(* Logix 5000 project; controller ILX69_PBM vendor 1 type 14 code 77 rev 16.3; software revision 16.05 *)
// ILX69-PBM Profibus Master Sample Ladder

TASK MainTask (continuous, watchdog 500 ms) : MainProgram

MODULES
   Controller : vendor 1 type 14 code 77 (CompactLogixL32EController 0, rev 16.3)
      LocalENB : 1769-L32E Ethernet Port (CompactLogixL32Ethernet 1, rev 16.3)
      Local : CompactBus (CompactVirtualAdapter 3, rev 16.3, Input RPI 5 ms)
         PBM : 1769-MODULE (Compact 1, rev 1.1, Output RPI 2 ms)   // Profibus Master
END_MODULES

TYPE EDIT_ILX69PBM_DATA :   // Array size should be the same as the address table size in fdt Configuration Manager.
STRUCT
   INPUT : SINT[5712];   // Input Data
   OUTPUT : SINT[5760];   // Output Data
END_STRUCT
END_TYPE

TYPE ILX69PBM_CONTROL :
STRUCT
   DisableProfibus : BOOL;   // Halt Profibus Communication
   ColdBoot : BOOL;   // Cold Boot Reset
   BackplaneBlock : ILX69PBM_CONTROL_BACKPLANE;   // Block Control
   DPV1 : ILX69PBM_CONTROL_DPV1;   // DPV1 Data
   SlaveDiagnostic : ILX69PBM_CONTROL_SLAVEDIAG;   // Slave Diagnostic Data
   SlaveControl : ILX69PBM_CONTROL_SLAVECONTROL;   // Slave Control
END_STRUCT
END_TYPE

TYPE ILX69PBM_CONTROL_BACKPLANE :   // Backplane Block Control
STRUCT
   DisableAutoTransfer : BOOL;   // Disable Automatic Block Transfer
   Input : ILX69PBM_CONTROL_BACKPLANE_INPUT;
   Output : ILX69PBM_CONTROL_BACKPLANE_OUTPUT;
END_STRUCT
END_TYPE

TYPE ILX69PBM_CONTROL_BACKPLANE_INPUT :
STRUCT
   BlockID : SINT;   // Requested Input Block Number. Use when DisableAutoTransfer is set.
   ReadBlock : BOOL;   // Initiate to receive the data from the requested Input Block Number. Use when DisableAutoTransfer is set.
END_STRUCT
END_TYPE

TYPE ILX69PBM_CONTROL_BACKPLANE_OUTPUT :
STRUCT
   BlockID : SINT;   // Command Output Block Number. Use when DisableAutoTransfer is set.
   WriteBlock : BOOL;   // Send current commanded output block to module. Use when DisableAutoTransfer is set.
   CommitToProfibus : BOOL;   // Commit output block data to Profibus. Use when DisableAutoTransfer is set.
END_STRUCT
END_TYPE

TYPE ILX69PBM_CONTROL_DPV1 :   // DPV1
STRUCT
   Read : ILX69PBM_CONTROL_DPV1_READ;   // DPV1 Read Request
   Write : ILX69PBM_CONTROL_DPV1_WRITE;   // DPV1 Write Request
   Alarm : ILX69PBM_CONTROL_DPV1_ALARM;   // DPV1 Alarm Response Request
END_STRUCT
END_TYPE

TYPE ILX69PBM_CONTROL_DPV1_ALARM :   // Alarm Response
STRUCT
   Initiate : BOOL;   // Initiate DPV1 Alarm Response
   MSGStatus : ILX69PBM_MESSAGE_STATUS;   // Message Status
   Request : ILX69PBM_CONTROL_DPV1_ALARM_REQUEST;   // Request
   Response : ILX69PBM_CONTROL_DPV1_ALARM_RESPONSE;   // Response
END_STRUCT
END_TYPE

TYPE ILX69PBM_CONTROL_DPV1_ALARM_REQUEST :   // DPV1 Alarm Response Request
STRUCT
   Status : DINT;   // Status
   Command : DINT;   // Message Command. Set to 0x221C
   SlaveAddress : SINT;   // Slave Address
   AlarmType : SINT;   // Type of the received alarm
   SlotNumber : SINT;   // Slot number of module causing the alarm
   Specifier : SINT;   // Alarm specifier
   Function : SINT;   // Reserved
   Reserved : SINT[3];   // Reserved
END_STRUCT
END_TYPE

TYPE ILX69PBM_CONTROL_DPV1_ALARM_RESPONSE :   // DPV1 Alarm Response Confirm
STRUCT
   Status : DINT;   // Status 0=OK
   Command : DINT;   // Should be 0x221D
   SlaveAddress : SINT;   // Slave Address
   AlarmType : SINT;   // Type of alarm received
   SlotNumber : SINT;   // Slot Number of module causing the alarm
   Specifier : SINT;   // Alarm specifier
   Function : SINT;   // Reserved
   ErrorDecode : SINT;   // 128 indicates DPV1 error
   ErrorCode1 : SINT;   // Error Code 1
   ErrorCode2 : SINT;   // Error Code 2
END_STRUCT
END_TYPE

TYPE ILX69PBM_CONTROL_DPV1_READ :   // DPV1 Read
STRUCT
   Initiate : BOOL;   // Initiate DPV1 Slave Read
   MSGStatus : ILX69PBM_MESSAGE_STATUS;   // Message Status
   Request : ILX69PBM_CONTROL_DPV1_READ_REQUEST;   // Request
   Response : ILX69PBM_CONTROL_DPV1_READ_RESPONSE;   // Response
END_STRUCT
END_TYPE

TYPE ILX69PBM_CONTROL_DPV1_READ_REQUEST :   // DPV1 Read Request
STRUCT
   Status : DINT;   // Status
   Command : DINT;   // Message Command. Set to 0x2210
   SlaveAddress : SINT;   // Slave Address
   SlotNumber : SINT;   // Slot Number
   Index : SINT;   // Index
   Length : SINT;   // Length
END_STRUCT
END_TYPE

TYPE ILX69PBM_CONTROL_DPV1_READ_RESPONSE :   // DPV1 Read Response
STRUCT
   Status : DINT;   // Status
   Command : DINT;   // Should be 0x2211
   SlaveAddress : SINT;   // Slave Address
   SlotNumber : SINT;   // Slot Number
   Index : SINT;   // Index
   Length : SINT;   // Length
   Data : SINT[100];   // Data or Error Codes (first 2 bytes)
END_STRUCT
END_TYPE

TYPE ILX69PBM_CONTROL_DPV1_WRITE :   // DPV1 Write
STRUCT
   Initiate : BOOL;   // Initiate DPV1 Slave Write
   MSGStatus : ILX69PBM_MESSAGE_STATUS;   // Message Status
   Request : ILX69PBM_CONTROL_DPV1_WRITE_REQUEST;   // Request
   Response : ILX69PBM_CONTROL_DPV1_WRITE_RESPONSE;   // Response
END_STRUCT
END_TYPE

TYPE ILX69PBM_CONTROL_DPV1_WRITE_REQUEST :   // DPV1 Write Request
STRUCT
   Status : DINT;   // Status
   Command : DINT;   // Message Command. Set to 0x2212
   SlaveAddress : SINT;   // Slave Address
   SlotNumber : SINT;   // Slot Number
   Index : SINT;   // Index
   Length : SINT;   // Length
   Data : SINT[100];   // Write Data
END_STRUCT
END_TYPE

TYPE ILX69PBM_CONTROL_DPV1_WRITE_RESPONSE :   // DPV1 Write Response
STRUCT
   Status : DINT;   // Status 0=OK
   Command : DINT;   // Should return 0x2213
   SlaveAddress : SINT;   // Slave Address
   SlotNumber : SINT;   // Slot Number
   Index : SINT;   // Index
   Length : SINT;   // Length
   ErrorDecode : SINT;   // Error 128=DPV1 error
   ErrorCode1 : SINT;   // Error Code 1
   ErrorCode2 : SINT;   // Error Code 2
   Reserved : SINT;   // Reserved
END_STRUCT
END_TYPE

TYPE ILX69PBM_CONTROL_SLAVECONTROL :   // Cyclic Slave Control
STRUCT
   SetSlaveControl : ILX69PBM_CONTROL_SLAVECONTROLBLOCK;   // Slave Control via Block Transfer
   SetSlaveControl_MSG : ILX69PBM_CONTROL_SLAVECONTROLMSG;   // Slave Global Control via MSG
END_STRUCT
END_TYPE

TYPE ILX69PBM_CONTROL_SLAVECONTROLBLOCK :
STRUCT
   Initiate : BOOL;   // Initiate Slave Control
   Address : SINT;   // Slave Address
   MSGStatus : ILX69PBM_MESSAGE_STATUS;   // Message Status
   SlaveCommand : ILX69PBM_CONTROL_SLAVECONTROLBLOCK_CMD;   // Slave Control Command
END_STRUCT
END_TYPE

TYPE ILX69PBM_CONTROL_SLAVECONTROLBLOCK_CMD :   // Slave Control Block Command
STRUCT
   ClearData : BOOL;   // Clear Output Data
   UnFreeze : BOOL;   // Unfreeze Input Data
   Freeze : BOOL;   // Freeze Input Data
   UnSync : BOOL;   // Neutralize the sync command or Unsync
   Sync : BOOL;   // Freeze Output Data until sync command is neutralized
   GroupSelect : SINT;   // Group Select
END_STRUCT
END_TYPE

TYPE ILX69PBM_CONTROL_SLAVECONTROLMSG :   // DPV0 Global Control
STRUCT
   Initiate : BOOL;   // Initiate Global Control
   MSGStatus : ILX69PBM_MESSAGE_STATUS;   // Message Status
   Request : ILX69PBM_CONTROL_SLAVECONTROLMSG_REQUEST;   // Request
   Response : ILX69PBM_CONTROL_SLAVECONTROLMSG_RESPONS;   // Response
END_STRUCT
END_TYPE

TYPE ILX69PBM_CONTROL_SLAVECONTROLMSG_CMD :   // Slave Control Message Command
STRUCT
   UnFreeze : BOOL;   // Unfreeze Input Data
   Freeze : BOOL;   // Freeze Input Data
   UnSync : BOOL;   // Neutralize the sync command or Unsync
   Sync : BOOL;   // Freeze Output Data until sync command is neutralized
   GroupSelect : SINT;   // Group Select
END_STRUCT
END_TYPE

TYPE ILX69PBM_CONTROL_SLAVECONTROLMSG_REQUEST :   // Global Control Request
STRUCT
   Status : DINT;   // Status
   Command : DINT;   // Message Command. Set to 0x2220
   Address : DINT;   // Slave Address
   Reserved : ILX69PBM_CONTROL_SLAVECONTROLMSG_RSVD;   // Reserved
   SlaveCommand : ILX69PBM_CONTROL_SLAVECONTROLMSG_CMD;   // Slave Command
END_STRUCT
END_TYPE

TYPE ILX69PBM_CONTROL_SLAVECONTROLMSG_RESPONS :   // DPV0 Slave Global Control Confirm
STRUCT
   Status : DINT;   // Status 0=OK
   Command : DINT;   // Should return 0x2221
END_STRUCT
END_TYPE

TYPE ILX69PBM_CONTROL_SLAVECONTROLMSG_RSVD :
STRUCT
   SyncCommand : DINT;   // Sync Command
   FreezeCommand : DINT;   // Freeze Command
   GroupSelect : DINT;   // Group selection
END_STRUCT
END_TYPE

TYPE ILX69PBM_CONTROL_SLAVEDIAG :   // Diagnostic Data
STRUCT
   GetSlaveDiag : ILX69PBM_CONTROL_SLAVEDIAG_BLOCK;   // Slave Diagnostic Data via Block Transfer
   GetSlaveDiagExtended_MSG : ILX69PBM_CONTROL_SLAVEDIAG_EXT;   // Slave Extended Diagnostic via MSG
END_STRUCT
END_TYPE

TYPE ILX69PBM_CONTROL_SLAVEDIAG_BLOCK :   // Slave Diagnostic Data
STRUCT
   Initiate : BOOL;   // Initiate Slave Diagnostic
   Address : SINT;   // Slave Address
   Function : SINT;   // Function: 0-Requested from Master 1-Requested from Slave
   MSGStatus : ILX69PBM_MESSAGE_STATUS;   // Message Status
   Response : ILX69PBM_CONTROL_SLAVEDIAG_BLOCKRESPONSE;   // Diagnostic Response
END_STRUCT
END_TYPE

TYPE ILX69PBM_CONTROL_SLAVEDIAG_BLOCKRESPONSE :   // Slave Diagnostic Reponse
STRUCT
   SlaveAddress : SINT;   // Slave address
   SlaveDiagnosticFailure : SINT;   // Slave Diag Failure
   StationNotExist : BOOL;   // No response
   StationNotReady : BOOL;   // Station not ready
   ConfigurationFault : BOOL;   // Configuration faulty
   ExtendedDiagnostic : BOOL;   // Extended diagnostic
   SyncFreezeNoSupport : BOOL;   // Sync,Freeze not supported
   InvalidResponse : BOOL;   // Response faulty
   ParamterFault : BOOL;   // Parameters faulty
   MasterLock : BOOL;   // Locked by a master
   ParameterRequest : BOOL;   // Request new parameter
   StaticDiagnostic : BOOL;   // Static diagnostic
   Slave : BOOL;   // Set to 1 by a slave
   Watchdog : BOOL;   // Watchdog ON/OFF
   FreezeMode : BOOL;   // Freeze mode active
   SyncMode : BOOL;   // Sync mode active
   Reserved : BOOL;   // Reserved
   SlaveDeactivated : BOOL;   // Slave deactivated
   Reserved0 : BOOL;   // Reserved
   Reserved1 : BOOL;   // Reserved
   Reserved2 : BOOL;   // Reserved
   Reserved3 : BOOL;   // Reserved
   Reserved4 : BOOL;   // Reserved
   Reserved5 : BOOL;   // Reserved
   Reserved6 : BOOL;   // Reserved
   ExtendedDiagnosticOverflow : BOOL;   // Extended diagnostic overflow
   MasterAddress : SINT;   // Corresponding master address
   IdentNumber : INT;   // PROFIBUS Ident number
END_STRUCT
END_TYPE

TYPE ILX69PBM_CONTROL_SLAVEDIAG_EXT :   // Slave Extended Diagnostic Data
STRUCT
   Initiate : BOOL;   // Initiate Slave Extended Diagnostic
   MSGStatus : ILX69PBM_MESSAGE_STATUS;   // Message Status
   Request : ILX69PBM_CONTROL_SLAVEDIAG_EXT_REQUEST;   // Request
   Response : ILX69PBM_CONTROL_SLAVEDIAG_EXT_RESPONSE;   // Reponse
END_STRUCT
END_TYPE

TYPE ILX69PBM_CONTROL_SLAVEDIAG_EXT_REQUEST :   // Slave Extended Diagnostic Request
STRUCT
   Status : DINT;   // Slave Status
   Command : DINT;   // Message Command. Set to 0x220a
   Address : DINT;   // Slave Address
   Flag : DINT;   // Flag
END_STRUCT
END_TYPE

TYPE ILX69PBM_CONTROL_SLAVEDIAG_EXT_RESPONSE :   // Slave Extented Diagnostic Response
STRUCT
   Status : DINT;   // Status 0=OK
   Command : DINT;   // Should return 0x220A
   SlaveAddress : DINT;   // Slave Address
   Diagnostic : SINT[256];   // Slave Diagnostic
END_STRUCT
END_TYPE

TYPE ILX69PBM_MESSAGE_STATUS :   // Message Status
STRUCT
   Done : BOOL;   // Message transmitted. Response is available
   Error : BOOL;   // Last message transmitted with an error
   DoneCount : DINT;   // Response OK Count
   ErrorCount : DINT;   // Error Count
END_STRUCT
END_TYPE

TYPE ILX69PBM_MODULEDEF :   // ILX69-PBM PROFIBUS Master Module Definition
STRUCT
   DATA : EDIT_ILX69PBM_DATA;   // Data
   STATUS : ILX69PBM_STATUS;   // Module Status
   CONTROL : ILX69PBM_CONTROL;   // Module Control
END_STRUCT
END_TYPE

TYPE ILX69PBM_SLAVE128 :
STRUCT
   Slave : BOOL[128];   // Slave
END_STRUCT
END_TYPE

TYPE ILX69PBM_STATUS :   // Status
STRUCT
   Communication : BOOL;   // Profibus communication is started and the module is engaged in cyclic data exchange with at least one Slave
   Running : BOOL;   // Running. Module is ready for communication.
   Ready : BOOL;   // Ready. Module is operational.
   FirmwareRevision : ILX69PBM_STATUS_FW_REVISION;   // Firmware Revision
   GlobalState : ILX69PBM_STATUS_GLOBAL_STATE;   // Global State
   DPV1AlarmIndication : ILX69PBM_STATUS_DPV1_ALARM_INDICATION;   // DPV1 Alarm Indication
   BackplaneBlock : ILX69PBM_STATUS_BACKPLANE;   // Backplane Block Status
END_STRUCT
END_TYPE

TYPE ILX69PBM_STATUS_BACKPLANE :   // Backplane Block Status
STRUCT
   Input : ILX69PBM_STATUS_BACKPLANE_INPUT;
   Output : ILX69PBM_STATUS_BACKPLANE_OUTPUT;
END_STRUCT
END_TYPE

TYPE ILX69PBM_STATUS_BACKPLANE_INPUT :   // Input Block Status
STRUCT
   ReturnedBlockID : SINT;   // Current Input block of module.
   BlockRead : BOOL;   // The requested block has been transferred to Data.Input Array with appropriate offset.
END_STRUCT
END_TYPE

TYPE ILX69PBM_STATUS_BACKPLANE_OUTPUT :   // Output Block Status
STRUCT
   CommittedToProfibus : BOOL;   // Output Data is committed to Profibus
   CurrentBlockToModule : BOOL;   // The current output block data is sent to the module but not committed to Profibus (if not block 0).
   BlockID : SINT;   // Current Output block of module.
END_STRUCT
END_TYPE

TYPE ILX69PBM_STATUS_DPV1_ALARM_INDICATION :   // DPV1 Alarm Indication
STRUCT
   AlarmIndication : BOOL;   // Indicates an alarm
   AlarmOverrun : BOOL;   // Overflow of the modules internal alarm buffer
   AlarmIndicationCounter : SINT;   // Alarm indication counter
   SlaveAddress : SINT;   // Address of Slave with Alarm
   SlotNumber : SINT;   // Slot Number
   SequenceNumber : SINT;   // Sequence Number
   AlarmType : SINT;   // Alarm Type
   AlarmSpecification : SINT;   // Alarm Specification
END_STRUCT
END_TYPE

TYPE ILX69PBM_STATUS_FW_REVISION :   // Firmware Major/Minor Revision
STRUCT
   FwMinor : SINT;   // Firmware Minor Revison
   FwMajor : SINT;   // Firmware Major Revison
END_STRUCT
END_TYPE

TYPE ILX69PBM_STATUS_GLOBAL_STATE :   // Global State
STRUCT
   ControlError : BOOL;   // Control error. Parameterization error
   AutoClearError : BOOL;   // Auto clear error. Module stopped communication with all slaves and reached the auto-clear-end state.
   NonExchangeError : BOOL;   // Non exchange error. At least one slave has not reached the data exchange state and no process data will be exchanged.
   FatalError : BOOL;   // Fatal error. Because of major bus error, no further bus communication is possible.
   EventError : BOOL;   // Event error. Bus short circuits detected
   HostNotReady : BOOL;   // Host not ready notification. The Application program is not ready to communicate
   Timeout : BOOL;   // Timeout.Overstepped timeout supervision value because of rejected PROFIBUS telegrams.
   Reserved1 : BOOL;   // Reserved
   MasterMainState : SINT;   // Master main state. 00hex: OFFLINE 40hex: STOP 80hex: CLEAR C0hex: OPERATE
   FaultySlaveAddress : SINT;   // Faulty remote address. 0 ... 125 Error detected with a Slave device 255 Error with Master.
   ErrorNumber : SINT;   // Error Number. See Manual for details.
   BusErrorCount : INT;   // Heavy bus error counter
   TimeoutCount : INT;   // Number of rejected PROFIBUS Telegr.
   SlaveConfiguration : ILX69PBM_SLAVE128;   // Slave Config
   SlaveState : ILX69PBM_SLAVE128;   // Slave State
   SlaveDiagnostic : ILX69PBM_SLAVE128;   // Slave Diagnostic
END_STRUCT
END_TYPE

TYPE ILX69PBM_UTIL :
STRUCT
   InputArray : ILX69PBM_UTIL_INPUT_ARRAY;   // Input from Module
   OutputArray : ILX69PBM_UTIL_OUTPUT_ARRAY;   // Output to Module
   InputOffset : INT;
   OutputOffset : INT;
   InputSize : INT;
   OutputSize : INT;
   InputDataSize : INT;
   InputCopyLength : INT;
   OutputDataSize : INT;
   OutputCopyLength : INT;
   OutputCopyLastLength : INT;
   OutputConnectionSize : INT;
   UTILOutputCopyLength : INT;
   SlaveDiagErrorTimer : TIMER;
   SlaveControlErrorTimer : TIMER;
   Config : ILX69PBM_UTIL_CONFIG;
END_STRUCT
END_TYPE

TYPE ILX69PBM_UTIL_CONFIG :   // Control
STRUCT
   MaxBlockTransferOut : SINT;   // Maximum Block Number Out. Calculated by total output bytes divided by 480.
   MaxBlockTransferIn : SINT;   // Maximum Block Number In. Calculated by total input bytes divided by 408.
   MaxBlockDataOut : SINT;
END_STRUCT
END_TYPE

TYPE ILX69PBM_UTIL_DEV_COMMAND_REGISTER :   // Device Command Register
STRUCT
   Reserved0 : BOOL;   // Reserved
   Reserved1 : BOOL;   // Reserved
   Reserved2 : BOOL;   // Reserved
   Reserved3 : BOOL;   // Reserved
   Reserved4 : BOOL;   // Reserved
   NotReady : BOOL;   // Application Not Ready
   Reserved5 : BOOL;   // Init ( Warm boot )
   Reset : BOOL;   // Reset ( Cold boot )
   HsReq0 : BOOL;   // Slave Diag Request
   HsReq1 : BOOL;   // Global Control Request
   HsReq2 : BOOL;   // Reserved
   HsReq3 : BOOL;   // Reserved
   HsReq4 : BOOL;   // Reserved
   HsReq5 : BOOL;   // Reserved
   HsReq6 : BOOL;   // Reserved
   HsReq7 : BOOL;   // Reserved
   BlockTransferOut : SINT;   // Reserved
   BlockTransferIn : SINT;   // Reserved
END_STRUCT
END_TYPE

TYPE ILX69PBM_UTIL_DEV_STATUS_REGISTER :   // Device Status Register
STRUCT
   Reserved0 : BOOL;   // Reserved
   Reserved1 : BOOL;   // Reserved
   Reserved2 : BOOL;   // Reserved
   Reserved3 : BOOL;   // Reserved
   Reserved4 : BOOL;   // Reserved
   Communication : BOOL;   // Communication
   Running : BOOL;   // Running
   Ready : BOOL;   // Ready
   HsAck0 : BOOL;   // Slave Diag Acknowledge
   HsAck1 : BOOL;   // Global Control Acknowledge
   HsAck2 : BOOL;
   HsAck3 : BOOL;
   HsAck4 : BOOL;
   HsAck5 : BOOL;
   HsAck6 : BOOL;
   HsAck7 : BOOL;
   BlockTransferOut : SINT;
   BlockTransferIn : SINT;
END_STRUCT
END_TYPE

TYPE ILX69PBM_UTIL_DPV1_ALARM_INDICATION :   // DPV1 Alarm Indication
STRUCT
   AlarmIndication : BOOL;   // Indicates an alarm
   Reserved1 : BOOL;   // Reserved
   Reserved2 : BOOL;   // Reserved
   Reserved3 : BOOL;   // Reserved
   Reserved4 : BOOL;   // Reserved
   Reserved5 : BOOL;   // Reserved
   Reserved6 : BOOL;   // Reserved
   AlarmOverrun : BOOL;   // Overflow of the modules internal alarm buffer
   AlarmIndicationCounter : SINT;   // Alarm indication counter
   SlaveAddress : SINT;   // Address of Slave with Alarm
   SlotNumber : SINT;   // Slot Number
   SequenceNumber : SINT;   // Sequence Number
   AlarmType : SINT;   // Alarm Type
   AlarmSpecification : SINT;   // Alarm Specification
   Reserved7 : SINT;   // Reserved
END_STRUCT
END_TYPE

TYPE ILX69PBM_UTIL_FW_REVISION_BPSIZE :   // Firmware Major/Minor Revision and Block Plane Size
STRUCT
   FwMinor : SINT;   // Firmware Minor Revison
   FwMajor : SINT;   // Firmware Major Revison
   Input : SINT;   // Number of Blocks required to transfer all Profibus cyclic Input data.
   Output : SINT;   // Number of Blocks required to transfer all Profibus cyclic Output data.
END_STRUCT
END_TYPE

TYPE ILX69PBM_UTIL_GLOBAL_CONTROL_COMMAND :   // Global Control Command
STRUCT
   SlaveAddress : SINT;   // Slave Address
   ControlCommand : SINT;   // Control Command to be sent
   GroupSelect : SINT;   // Group Select
   Reserved1 : SINT;   // Reserved
END_STRUCT
END_TYPE

TYPE ILX69PBM_UTIL_GLOBAL_STATE_FIELD :   // PROFIBUS Master Global State Field
STRUCT
   ControlError : BOOL;   // Control error
   AutoClearError : BOOL;   // Auto clear error
   NonExchangeError : BOOL;   // Non exchange error
   FatalError : BOOL;   // Fatal error
   EventError : BOOL;   // Event error
   HostNotReady : BOOL;   // Host not ready notification
   Timeout : BOOL;   // Timeout
   Reserved1 : BOOL;   // Reserved
   MasterMainState : SINT;   // Master main state
   FaultySlaveAddress : SINT;   // Faulty remote address
   ErrorNumber : SINT;   // Error Number
   BusErrorCount : INT;   // Heavy bus error counter
   TimeoutCount : INT;   // Number of rejected PROFIBUS Telegr.
   Reserved : SINT[8];   // Reserved
   SlaveConfiguration : ILX69PBM_SLAVE128;   // Slave Config
   SlaveState : ILX69PBM_SLAVE128;   // Slave State
   SlaveDiagnostic : ILX69PBM_SLAVE128;   // Slave Diag
END_STRUCT
END_TYPE

TYPE ILX69PBM_UTIL_INPUT_ARRAY :   // Input Array
STRUCT
   DeviceStatusRegister : ILX69PBM_UTIL_DEV_STATUS_REGISTER;   // Device Status
   FirmwareRevBPSize : ILX69PBM_UTIL_FW_REVISION_BPSIZE;   // Firmware Revision and Block Size
   GlobalStateField : ILX69PBM_UTIL_GLOBAL_STATE_FIELD;   // Global State Field
   SlaveDiagnostic : ILX69PBM_UTIL_SLAVE_DIAG_DATA;   // Slave Diagnostic
   DPV1AlarmIndication : ILX69PBM_UTIL_DPV1_ALARM_INDICATION;   // DPV1 Alarm Indication
   InputData : INT[204];   // PROFIBUS Input data.
END_STRUCT
END_TYPE

TYPE ILX69PBM_UTIL_OUTPUT_ARRAY :
STRUCT
   DeviceCommandRegister : ILX69PBM_UTIL_DEV_COMMAND_REGISTER;   // Command Register
   DiagnosticSlaveAddress : ILX69PBM_UTIL_SLAVE_DIAG_COMMAND;   // Slave Address
   GlobalControlCommand : ILX69PBM_UTIL_GLOBAL_CONTROL_COMMAND;   // Global Control Command
   Reserved : SINT[4];   // Reserved
   OutputData : INT[240];   // PROFIBUS Output data.
END_STRUCT
END_TYPE

TYPE ILX69PBM_UTIL_SLAVE_DIAG_COMMAND :   // Requested address for SlaveDiagnostic
STRUCT
   SlaveAddress : SINT;   // Slave Address
   DiagnosticMode : SINT;   // Diagnostic Mode
   Reserved1 : SINT;   // Reserved
   Reserved2 : SINT;   // Reserved
END_STRUCT
END_TYPE

TYPE ILX69PBM_UTIL_SLAVE_DIAG_DATA :   // Slave standard diagnostic data according to PROFIBUS norm.
STRUCT
   SlaveAddress : SINT;   // Slave address
   SlaveDiagnosticFailure : SINT;   // Slave Diag Failure
   Sta1_StationNotExist : BOOL;   // No response
   Sta1_StationNotReady : BOOL;   // Station not ready
   Sta1_ConfigurationFault : BOOL;   // Configuration faulty
   Sta1_ExtendedDiagnostic : BOOL;   // Extended diagnostic
   Sta1_SyncFreezeNoSupport : BOOL;   // Sync,Freeze not supported
   Sta1_InvalidResponse : BOOL;   // Response faulty
   Sta1_ParamterFault : BOOL;   // Parameters faulty
   Sta1_MasterLock : BOOL;   // Locked by a master
   Sta2_ParameterRequest : BOOL;   // Request new parameter
   Sta2_StaticDiagnostic : BOOL;   // Static diagnostic
   Sta2_Slave : BOOL;   // Set to 1 by a slave
   Sta2_Watchdog : BOOL;   // Watchdog ON/OFF
   Sta2_FreezeMode : BOOL;   // Freeze mode active
   Sta2_SyncMode : BOOL;   // Sync mode active
   Sta2_Reserved : BOOL;   // Reserved
   Sta2_SlaveDeactivated : BOOL;   // Slave deactivated
   Sta3_Reserved0 : BOOL;   // Reserved
   Sta3_Reserved1 : BOOL;   // Reserved
   Sta3_Reserved2 : BOOL;   // Reserved
   Sta3_Reserved3 : BOOL;   // Reserved
   Sta3_Reserved4 : BOOL;   // Reserved
   Sta3_Reserved5 : BOOL;   // Reserved
   Sta3_Reserved6 : BOOL;   // Reserved
   Sta3_ExtendedDiagnosticOverflow : BOOL;   // Extended diagnostic overflow
   MasterAddress : SINT;   // Corresponding master address
   IdentNumber : INT;   // PROFIBUS Ident number
END_STRUCT
END_TYPE

ADD_ON_INSTRUCTION AOIILX69PBM   (* revision 1.9, ExecutePrescan *)
// Add-On instruction for ILX69-PBM ProSoft module
// Revision note:
// V1.9 Unlocked AOI
// V1.8 Moved FLL UTIL.Output Array
// V1.7 Use local BlockID increment latch
// V1.6 Clear AOI UTIL local tag
VAR_IN_OUT
   ILX69PBM : ILX69PBM_MODULEDEF; {required}
   Connection_Input : INT[248]; {required}
        [0].5   // Communication
        [0].6   // Running
        [0].7   // Ready
   Connection_Output : INT[248]; {required}
   MSGSlaveDiagRequest : MESSAGE; {required}   // Slave Diagnostic Request Message
   MSGGlobalControl : MESSAGE; {required}   // Slave Global Control Message
   MSGDPV1Read : MESSAGE; {required}   // DPV1 Read Message
   MSGDPV1Write : MESSAGE; {required}   // DPV1 Write Message
   MSGDPV1Alarm : MESSAGE; {required}   // DPV1 Alarm Response Message
END_VAR
VAR
   UTIL : ILX69PBM_UTIL;
   InputBlockIDIncrementComplete : BOOL;
END_VAR

ROUTINE Logic   (* ladder *)
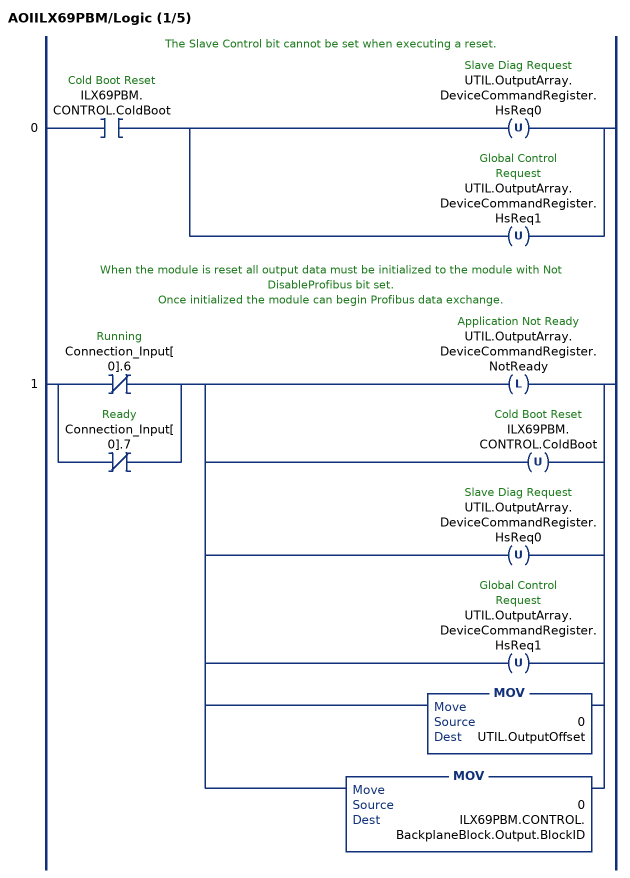
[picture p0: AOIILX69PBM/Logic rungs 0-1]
   // The Slave Control bit cannot be set when executing a reset.
   0: XIC(ILX69PBM.CONTROL.ColdBoot)[OTU(UTIL.OutputArray.DeviceCommandRegister.HsReq0) ,OTU(UTIL.OutputArray.DeviceCommandRegister.HsReq1) ];
   // When the module is reset all output data must be initialized to the module with Not DisableProfibus bit set.
   // Once initialized the module can begin Profibus data exchange.
   1: [XIO(Connection_Input[0].6) ,XIO(Connection_Input[0].7) ][OTL(UTIL.OutputArray.DeviceCommandRegister.NotReady) ,OTU(ILX69PBM.CONTROL.ColdBoot) ,OTU(UTIL.OutputArray.DeviceCommandRegister.HsReq0) ,OTU(UTIL.OutputArray.DeviceCommandRegister.HsReq1) ,MOV(0,UTIL.OutputOffset) ,MOV(0,ILX69PBM.CONTROL.BackplaneBlock.Output.BlockID) ];
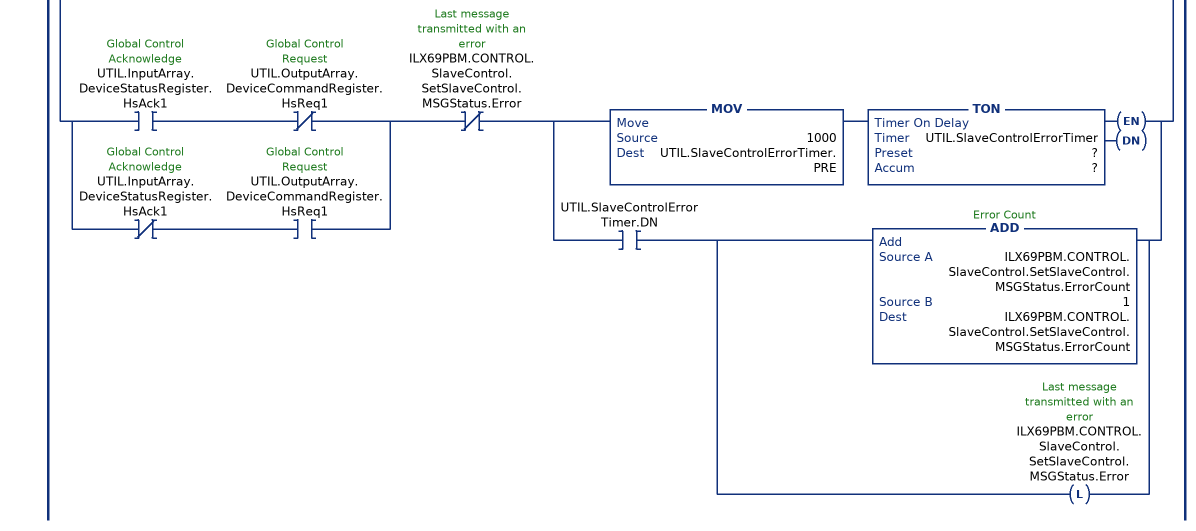
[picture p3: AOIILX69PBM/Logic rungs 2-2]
   // Handle Block Slave Diagnostic and Control
   2: [[XIC(ILX69PBM.CONTROL.SlaveDiagnostic.GetSlaveDiag.Initiate) [XIC(UTIL.OutputArray.DeviceCommandRegister.HsReq0) OTU(UTIL.OutputArray.DeviceCommandRegister.HsReq0) OTU(ILX69PBM.CONTROL.SlaveDiagnostic.GetSlaveDiag.Initiate) ,XIC(ILX69PBM.CONTROL.SlaveDiagnostic.GetSlaveDiag.Initiate) XIO(UTIL.OutputArray.DeviceCommandRegister.HsReq0) OTL(UTIL.OutputArray.DeviceCommandRegister.HsReq0) OTU(ILX69PBM.CONTROL.SlaveDiagnostic.GetSlaveDiag.Initiate) ] [OTU(ILX69PBM.CONTROL.SlaveDiagnostic.GetSlaveDiag.MSGStatus.Error) ,OTU(ILX69PBM.CONTROL.SlaveDiagnostic.GetSlaveDiag.MSGStatus.Done) ] ,[[XIC(UTIL.InputArray.DeviceStatusRegister.HsAck0) XIC(UTIL.OutputArray.DeviceCommandRegister.HsReq0) ,XIO(UTIL.InputArray.DeviceStatusRegister.HsAck0) XIO(UTIL.OutputArray.DeviceCommandRegister.HsReq0) ] [XIO(ILX69PBM.CONTROL.SlaveDiagnostic.GetSlaveDiag.MSGStatus.Done) ADD(ILX69PBM.CONTROL.SlaveDiagnostic.GetSlaveDiag.MSGStatus.DoneCount,1,ILX69PBM.CONTROL.SlaveDiagnostic.GetSlaveDiag.MSGStatus.DoneCount) ,OTL(ILX69PBM.CONTROL.SlaveDiagnostic.GetSlaveDiag.MSGStatus.Done) ] ,[XIC(UTIL.InputArray.DeviceStatusRegister.HsAck0) XIO(UTIL.OutputArray.DeviceCommandRegister.HsReq0) ,XIO(UTIL.InputArray.DeviceStatusRegister.HsAck0) XIC(UTIL.OutputArray.DeviceCommandRegister.HsReq0) ] XIO(ILX69PBM.CONTROL.SlaveDiagnostic.GetSlaveDiag.MSGStatus.Error) [MOV(1000,UTIL.SlaveDiagErrorTimer.PRE) TON(UTIL.SlaveDiagErrorTimer,?,?) ,XIC(UTIL.SlaveDiagErrorTimer.DN) [ADD(ILX69PBM.CONTROL.SlaveDiagnostic.GetSlaveDiag.MSGStatus.ErrorCount,1,ILX69PBM.CONTROL.SlaveDiagnostic.GetSlaveDiag.MSGStatus.ErrorCount) ,OTL(ILX69PBM.CONTROL.SlaveDiagnostic.GetSlaveDiag.MSGStatus.Error) ] ] ] ] ,[XIC(ILX69PBM.CONTROL.SlaveControl.SetSlaveControl.Initiate) [XIC(UTIL.OutputArray.DeviceCommandRegister.HsReq1) OTU(UTIL.OutputArray.DeviceCommandRegister.HsReq1) OTU(ILX69PBM.CONTROL.SlaveControl.SetSlaveControl.Initiate) ,XIC(ILX69PBM.CONTROL.SlaveControl.SetSlaveControl.Initiate) XIO(UTIL.OutputArray.DeviceCommandRegister.HsReq1) OTL(UTIL.OutputArray.DeviceCommandRegister.HsReq1) OTU(ILX69PBM.CONTROL.SlaveControl.SetSlaveControl.Initiate) ] [OTU(ILX69PBM.CONTROL.SlaveControl.SetSlaveControl.MSGStatus.Error) ,OTU(ILX69PBM.CONTROL.SlaveControl.SetSlaveControl.MSGStatus.Done) ] ,[[XIC(UTIL.InputArray.DeviceStatusRegister.HsAck1) XIC(UTIL.OutputArray.DeviceCommandRegister.HsReq1) ,XIO(UTIL.InputArray.DeviceStatusRegister.HsAck1) XIO(UTIL.OutputArray.DeviceCommandRegister.HsReq1) ] [XIO(ILX69PBM.CONTROL.SlaveControl.SetSlaveControl.MSGStatus.Done) ADD(ILX69PBM.CONTROL.SlaveControl.SetSlaveControl.MSGStatus.DoneCount,1,ILX69PBM.CONTROL.SlaveControl.SetSlaveControl.MSGStatus.DoneCount) ,OTL(ILX69PBM.CONTROL.SlaveControl.SetSlaveControl.MSGStatus.Done) ] ,[XIC(UTIL.InputArray.DeviceStatusRegister.HsAck1) XIO(UTIL.OutputArray.DeviceCommandRegister.HsReq1) ,XIO(UTIL.InputArray.DeviceStatusRegister.HsAck1) XIC(UTIL.OutputArray.DeviceCommandRegister.HsReq1) ] XIO(ILX69PBM.CONTROL.SlaveControl.SetSlaveControl.MSGStatus.Error) [MOV(1000,UTIL.SlaveControlErrorTimer.PRE) TON(UTIL.SlaveControlErrorTimer,?,?) ,XIC(UTIL.SlaveControlErrorTimer.DN) [ADD(ILX69PBM.CONTROL.SlaveControl.SetSlaveControl.MSGStatus.ErrorCount,1,ILX69PBM.CONTROL.SlaveControl.SetSlaveControl.MSGStatus.ErrorCount) ,OTL(ILX69PBM.CONTROL.SlaveControl.SetSlaveControl.MSGStatus.Error) ] ] ] ] ];
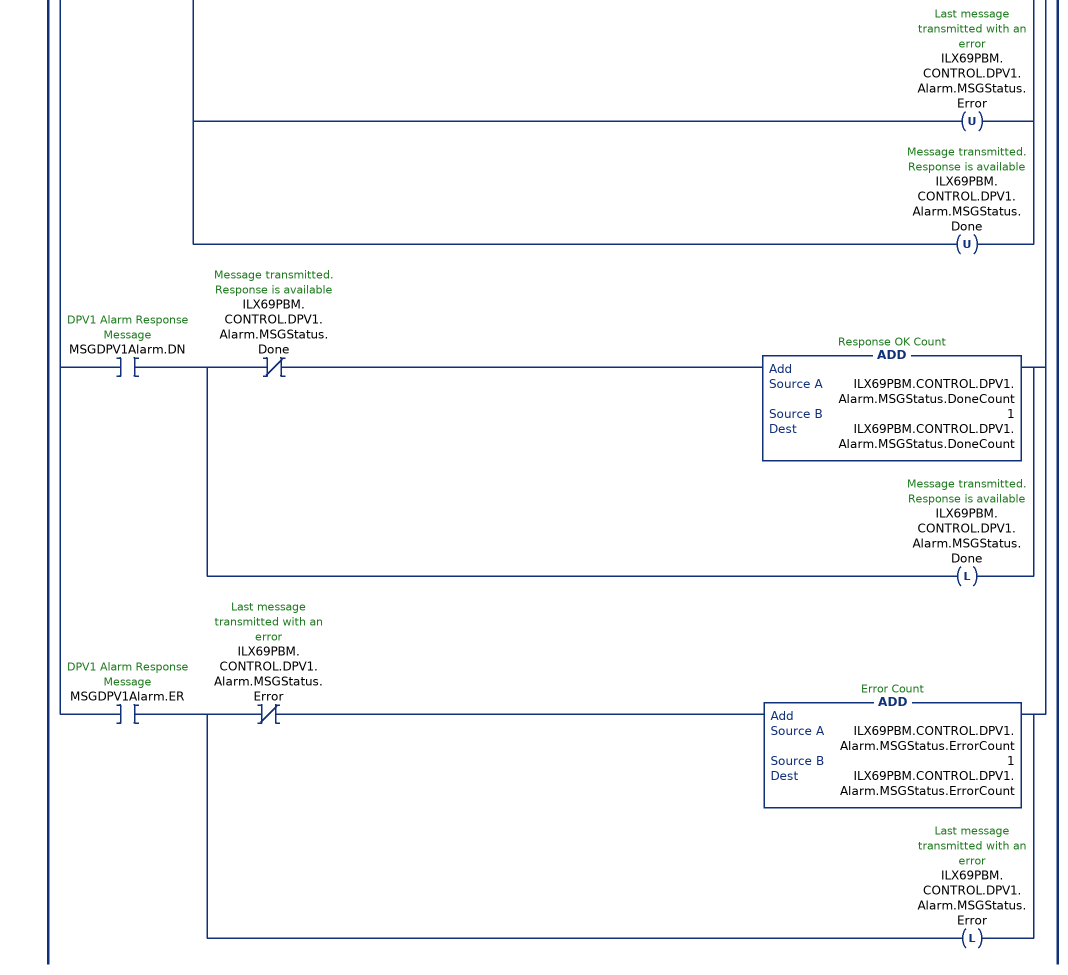
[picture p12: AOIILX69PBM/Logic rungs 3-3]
   // Message Handling
   3: [[XIC(ILX69PBM.CONTROL.SlaveDiagnostic.GetSlaveDiagExtended_MSG.Initiate) [MOV(8714,ILX69PBM.CONTROL.SlaveDiagnostic.GetSlaveDiagExtended_MSG.Request.Command) ,MSG(MSGSlaveDiagRequest) ,OTU(ILX69PBM.CONTROL.SlaveDiagnostic.GetSlaveDiagExtended_MSG.Initiate) ,OTU(ILX69PBM.CONTROL.SlaveDiagnostic.GetSlaveDiagExtended_MSG.MSGStatus.Error) ,OTU(ILX69PBM.CONTROL.SlaveDiagnostic.GetSlaveDiagExtended_MSG.MSGStatus.Done) ] ,XIC(MSGSlaveDiagRequest.DN) [XIO(ILX69PBM.CONTROL.SlaveDiagnostic.GetSlaveDiagExtended_MSG.MSGStatus.Done) ADD(ILX69PBM.CONTROL.SlaveDiagnostic.GetSlaveDiagExtended_MSG.MSGStatus.DoneCount,1,ILX69PBM.CONTROL.SlaveDiagnostic.GetSlaveDiagExtended_MSG.MSGStatus.DoneCount) ,OTL(ILX69PBM.CONTROL.SlaveDiagnostic.GetSlaveDiagExtended_MSG.MSGStatus.Done) ] ,XIC(MSGSlaveDiagRequest.ER) [XIO(ILX69PBM.CONTROL.SlaveDiagnostic.GetSlaveDiagExtended_MSG.MSGStatus.Error) ADD(ILX69PBM.CONTROL.SlaveDiagnostic.GetSlaveDiagExtended_MSG.MSGStatus.ErrorCount,1,ILX69PBM.CONTROL.SlaveDiagnostic.GetSlaveDiagExtended_MSG.MSGStatus.ErrorCount) ,OTL(ILX69PBM.CONTROL.SlaveDiagnostic.GetSlaveDiagExtended_MSG.MSGStatus.Error) ] ] ,[XIC(ILX69PBM.CONTROL.SlaveControl.SetSlaveControl_MSG.Initiate) [MOV(8736,ILX69PBM.CONTROL.SlaveControl.SetSlaveControl_MSG.Request.Command) ,[XIC(ILX69PBM.CONTROL.SlaveControl.SetSlaveControl_MSG.Request.SlaveCommand.UnFreeze) MVM(4,4,ILX69PBM.CONTROL.SlaveControl.SetSlaveControl_MSG.Request.Reserved.FreezeCommand) ,XIO(ILX69PBM.CONTROL.SlaveControl.SetSlaveControl_MSG.Request.SlaveCommand.UnFreeze) MVM(0,4,ILX69PBM.CONTROL.SlaveControl.SetSlaveControl_MSG.Request.Reserved.FreezeCommand) ] ,[XIC(ILX69PBM.CONTROL.SlaveControl.SetSlaveControl_MSG.Request.SlaveCommand.Freeze) MVM(8,8,ILX69PBM.CONTROL.SlaveControl.SetSlaveControl_MSG.Request.Reserved.FreezeCommand) ,XIO(ILX69PBM.CONTROL.SlaveControl.SetSlaveControl_MSG.Request.SlaveCommand.Freeze) MVM(0,8,ILX69PBM.CONTROL.SlaveControl.SetSlaveControl_MSG.Request.Reserved.FreezeCommand) ] ,[XIC(ILX69PBM.CONTROL.SlaveControl.SetSlaveControl_MSG.Request.SlaveCommand.UnSync) MVM(16#10,16#10,ILX69PBM.CONTROL.SlaveControl.SetSlaveControl_MSG.Request.Reserved.SyncCommand) ,XIO(ILX69PBM.CONTROL.SlaveControl.SetSlaveControl_MSG.Request.SlaveCommand.UnSync) MVM(0,16#10,ILX69PBM.CONTROL.SlaveControl.SetSlaveControl_MSG.Request.Reserved.SyncCommand) ] ,[XIC(ILX69PBM.CONTROL.SlaveControl.SetSlaveControl_MSG.Request.SlaveCommand.Sync) MVM(16#20,16#20,ILX69PBM.CONTROL.SlaveControl.SetSlaveControl_MSG.Request.Reserved.SyncCommand) ,XIO(ILX69PBM.CONTROL.SlaveControl.SetSlaveControl_MSG.Request.SlaveCommand.Sync) MVM(0,16#20,ILX69PBM.CONTROL.SlaveControl.SetSlaveControl_MSG.Request.Reserved.SyncCommand) ] ,MOV(ILX69PBM.CONTROL.SlaveControl.SetSlaveControl_MSG.Request.SlaveCommand.GroupSelect,ILX69PBM.CONTROL.SlaveControl.SetSlaveControl_MSG.Request.Reserved.GroupSelect) ,MSG(MSGGlobalControl) ,OTU(ILX69PBM.CONTROL.SlaveControl.SetSlaveControl_MSG.Initiate) ,OTU(ILX69PBM.CONTROL.SlaveControl.SetSlaveControl_MSG.MSGStatus.Error) ,OTU(ILX69PBM.CONTROL.SlaveControl.SetSlaveControl_MSG.MSGStatus.Done) ] ,XIC(MSGGlobalControl.DN) [XIO(ILX69PBM.CONTROL.SlaveControl.SetSlaveControl_MSG.MSGStatus.Done) ADD(ILX69PBM.CONTROL.SlaveControl.SetSlaveControl_MSG.MSGStatus.DoneCount,1,ILX69PBM.CONTROL.SlaveControl.SetSlaveControl_MSG.MSGStatus.DoneCount) ,OTL(ILX69PBM.CONTROL.SlaveControl.SetSlaveControl_MSG.MSGStatus.Done) ] ,XIC(MSGGlobalControl.ER) [XIO(ILX69PBM.CONTROL.SlaveControl.SetSlaveControl_MSG.MSGStatus.Error) ADD(ILX69PBM.CONTROL.SlaveControl.SetSlaveControl_MSG.MSGStatus.ErrorCount,1,ILX69PBM.CONTROL.SlaveControl.SetSlaveControl_MSG.MSGStatus.ErrorCount) ,OTL(ILX69PBM.CONTROL.SlaveControl.SetSlaveControl_MSG.MSGStatus.Error) ] ] ,[XIC(ILX69PBM.CONTROL.DPV1.Read.Initiate) [MOV(8720,ILX69PBM.CONTROL.DPV1.Read.Request.Command) ,MSG(MSGDPV1Read) ,OTU(ILX69PBM.CONTROL.DPV1.Read.Initiate) ,OTU(ILX69PBM.CONTROL.DPV1.Read.MSGStatus.Error) ,OTU(ILX69PBM.CONTROL.DPV1.Read.MSGStatus.Done) ] ,XIC(MSGDPV1Read.DN) [XIO(ILX69PBM.CONTROL.DPV1.Read.MSGStatus.Done) ADD(ILX69PBM.CONTROL.DPV1.Read.MSGStatus.DoneCount,1,ILX69PBM.CONTROL.DPV1.Read.MSGStatus.DoneCount) ,OTL(ILX69PBM.CONTROL.DPV1.Read.MSGStatus.Done) ] ,XIC(MSGDPV1Read.ER) [XIO(ILX69PBM.CONTROL.DPV1.Read.MSGStatus.Error) ADD(ILX69PBM.CONTROL.DPV1.Read.MSGStatus.ErrorCount,1,ILX69PBM.CONTROL.DPV1.Read.MSGStatus.ErrorCount) ,OTL(ILX69PBM.CONTROL.DPV1.Read.MSGStatus.Error) ] ] ,[XIC(ILX69PBM.CONTROL.DPV1.Write.Initiate) [CPT(MSGDPV1Write.REQ_LEN,12+ILX69PBM.CONTROL.DPV1.Write.Request.Length) [LES(MSGDPV1Write.REQ_LEN,12) MOV(12,MSGDPV1Write.REQ_LEN) ,GRT(MSGDPV1Write.REQ_LEN,112) MOV(112,MSGDPV1Write.REQ_LEN) ] ,MOV(8722,ILX69PBM.CONTROL.DPV1.Write.Request.Command) ,MSG(MSGDPV1Write) ,OTU(ILX69PBM.CONTROL.DPV1.Write.Initiate) ,OTU(ILX69PBM.CONTROL.DPV1.Write.MSGStatus.Error) ,OTU(ILX69PBM.CONTROL.DPV1.Write.MSGStatus.Done) ] ,XIC(MSGDPV1Write.DN) [XIO(ILX69PBM.CONTROL.DPV1.Write.MSGStatus.Done) ADD(ILX69PBM.CONTROL.DPV1.Write.MSGStatus.DoneCount,1,ILX69PBM.CONTROL.DPV1.Write.MSGStatus.DoneCount) ,OTL(ILX69PBM.CONTROL.DPV1.Write.MSGStatus.Done) ] ,XIC(MSGDPV1Write.ER) [XIO(ILX69PBM.CONTROL.DPV1.Write.MSGStatus.Error) ADD(ILX69PBM.CONTROL.DPV1.Write.MSGStatus.ErrorCount,1,ILX69PBM.CONTROL.DPV1.Write.MSGStatus.ErrorCount) ,OTL(ILX69PBM.CONTROL.DPV1.Write.MSGStatus.Error) ] ] ,[XIC(ILX69PBM.CONTROL.DPV1.Alarm.Initiate) [MOV(8732,ILX69PBM.CONTROL.DPV1.Alarm.Request.Command) ,MSG(MSGDPV1Alarm) ,OTU(ILX69PBM.CONTROL.DPV1.Alarm.Initiate) ,OTU(ILX69PBM.CONTROL.DPV1.Alarm.MSGStatus.Error) ,OTU(ILX69PBM.CONTROL.DPV1.Alarm.MSGStatus.Done) ] ,XIC(MSGDPV1Alarm.DN) [XIO(ILX69PBM.CONTROL.DPV1.Alarm.MSGStatus.Done) ADD(ILX69PBM.CONTROL.DPV1.Alarm.MSGStatus.DoneCount,1,ILX69PBM.CONTROL.DPV1.Alarm.MSGStatus.DoneCount) ,OTL(ILX69PBM.CONTROL.DPV1.Alarm.MSGStatus.Done) ] ,XIC(MSGDPV1Alarm.ER) [XIO(ILX69PBM.CONTROL.DPV1.Alarm.MSGStatus.Error) ADD(ILX69PBM.CONTROL.DPV1.Alarm.MSGStatus.ErrorCount,1,ILX69PBM.CONTROL.DPV1.Alarm.MSGStatus.ErrorCount) ,OTL(ILX69PBM.CONTROL.DPV1.Alarm.MSGStatus.Error) ] ] ];
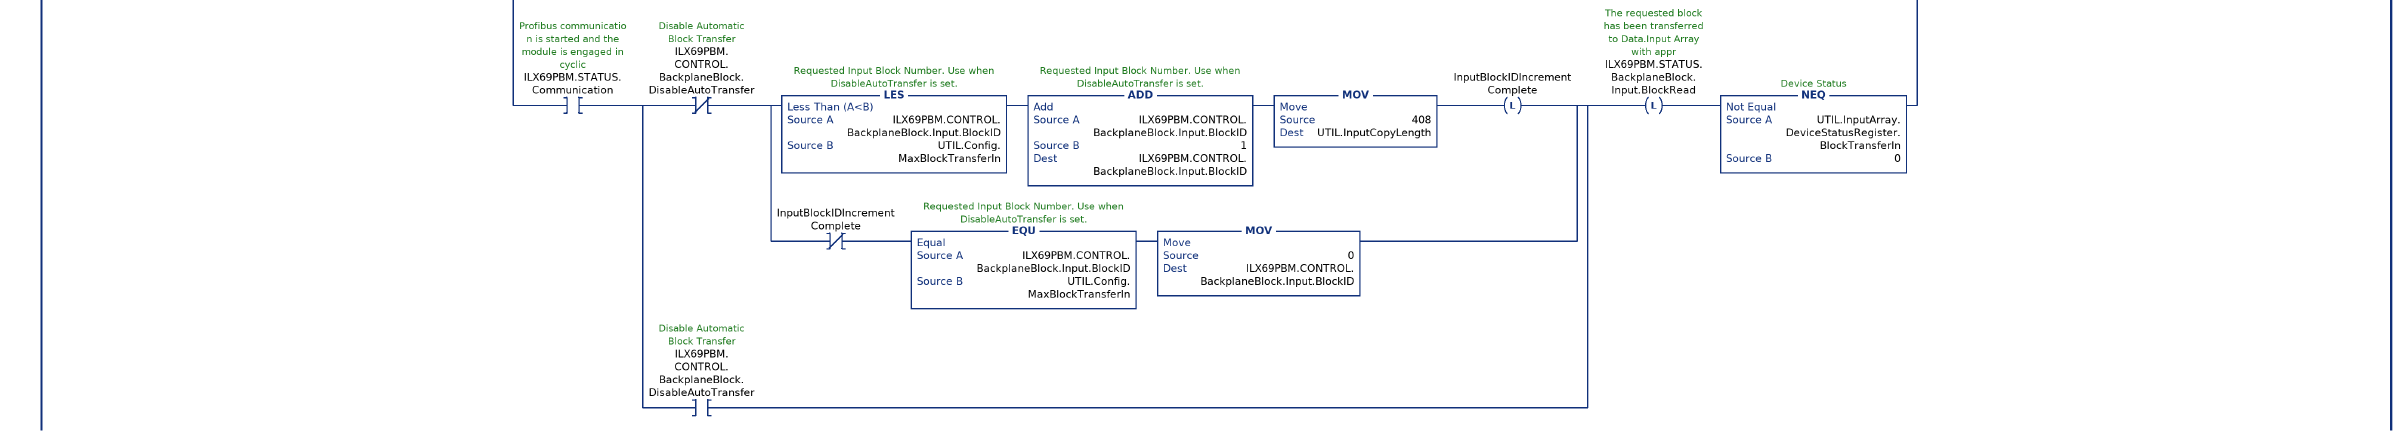
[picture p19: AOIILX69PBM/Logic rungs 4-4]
   // Handle Input Data
   4: [COP(Connection_Input[0],UTIL.InputArray,1) OTU(InputBlockIDIncrementComplete) ,[[XIC(UTIL.InputArray.DeviceStatusRegister.Communication) XIO(ILX69PBM.STATUS.Communication) OTL(ILX69PBM.STATUS.Communication) ,XIO(UTIL.InputArray.DeviceStatusRegister.Communication) XIC(ILX69PBM.STATUS.Communication) OTU(ILX69PBM.STATUS.Communication) ] ,[XIC(UTIL.InputArray.DeviceStatusRegister.Running) XIO(ILX69PBM.STATUS.Running) OTL(ILX69PBM.STATUS.Running) ,XIO(UTIL.InputArray.DeviceStatusRegister.Running) XIC(ILX69PBM.STATUS.Running) OTU(ILX69PBM.STATUS.Running) ] ,[XIC(UTIL.InputArray.DeviceStatusRegister.Ready) XIO(ILX69PBM.STATUS.Ready) OTL(ILX69PBM.STATUS.Ready) ,XIO(UTIL.InputArray.DeviceStatusRegister.Ready) XIC(ILX69PBM.STATUS.Ready) OTU(ILX69PBM.STATUS.Ready) ] ,COP(UTIL.InputArray.DeviceStatusRegister.BlockTransferOut,ILX69PBM.STATUS.BackplaneBlock.Output.BlockID,1) COP(UTIL.InputArray.DeviceStatusRegister.BlockTransferIn,ILX69PBM.STATUS.BackplaneBlock.Input.ReturnedBlockID,1) ] ,COP(UTIL.InputArray.FirmwareRevBPSize,ILX69PBM.STATUS.FirmwareRevision,1) ,[[XIC(UTIL.InputArray.GlobalStateField.ControlError) XIO(ILX69PBM.STATUS.GlobalState.ControlError) OTL(ILX69PBM.STATUS.GlobalState.ControlError) ,XIO(UTIL.InputArray.GlobalStateField.ControlError) XIC(ILX69PBM.STATUS.GlobalState.ControlError) OTU(ILX69PBM.STATUS.GlobalState.ControlError) ] ,[XIC(UTIL.InputArray.GlobalStateField.AutoClearError) XIO(ILX69PBM.STATUS.GlobalState.AutoClearError) OTL(ILX69PBM.STATUS.GlobalState.AutoClearError) ,XIO(UTIL.InputArray.GlobalStateField.AutoClearError) XIC(ILX69PBM.STATUS.GlobalState.AutoClearError) OTU(ILX69PBM.STATUS.GlobalState.AutoClearError) ] ,[XIC(UTIL.InputArray.GlobalStateField.NonExchangeError) XIO(ILX69PBM.STATUS.GlobalState.NonExchangeError) OTL(ILX69PBM.STATUS.GlobalState.NonExchangeError) ,XIO(UTIL.InputArray.GlobalStateField.NonExchangeError) XIC(ILX69PBM.STATUS.GlobalState.NonExchangeError) OTU(ILX69PBM.STATUS.GlobalState.NonExchangeError) ] ,[XIC(UTIL.InputArray.GlobalStateField.FatalError) XIO(ILX69PBM.STATUS.GlobalState.FatalError) OTL(ILX69PBM.STATUS.GlobalState.FatalError) ,XIO(UTIL.InputArray.GlobalStateField.FatalError) XIC(ILX69PBM.STATUS.GlobalState.FatalError) OTU(ILX69PBM.STATUS.GlobalState.FatalError) ] ,[XIC(UTIL.InputArray.GlobalStateField.EventError) XIO(ILX69PBM.STATUS.GlobalState.EventError) OTL(ILX69PBM.STATUS.GlobalState.EventError) ,XIO(UTIL.InputArray.GlobalStateField.EventError) XIC(ILX69PBM.STATUS.GlobalState.EventError) OTU(ILX69PBM.STATUS.GlobalState.EventError) ] ,[XIC(UTIL.InputArray.GlobalStateField.HostNotReady) XIO(ILX69PBM.STATUS.GlobalState.HostNotReady) OTL(ILX69PBM.STATUS.GlobalState.HostNotReady) ,XIO(UTIL.InputArray.GlobalStateField.HostNotReady) XIC(ILX69PBM.STATUS.GlobalState.HostNotReady) OTU(ILX69PBM.STATUS.GlobalState.HostNotReady) ] ,[XIC(UTIL.InputArray.GlobalStateField.Timeout) XIO(ILX69PBM.STATUS.GlobalState.Timeout) OTL(ILX69PBM.STATUS.GlobalState.Timeout) ,XIO(UTIL.InputArray.GlobalStateField.Timeout) XIC(ILX69PBM.STATUS.GlobalState.Timeout) OTU(ILX69PBM.STATUS.GlobalState.Timeout) ] ,COP(UTIL.InputArray.GlobalStateField.MasterMainState,ILX69PBM.STATUS.GlobalState.MasterMainState,7) ,COP(UTIL.InputArray.GlobalStateField.SlaveConfiguration,ILX69PBM.STATUS.GlobalState.SlaveConfiguration,3) ] ,COP(UTIL.InputArray.SlaveDiagnostic,ILX69PBM.CONTROL.SlaveDiagnostic.GetSlaveDiag.Response,1) ,[[XIC(UTIL.InputArray.DPV1AlarmIndication.AlarmIndication) XIO(ILX69PBM.STATUS.DPV1AlarmIndication.AlarmIndication) OTL(ILX69PBM.STATUS.DPV1AlarmIndication.AlarmIndication) ,XIO(UTIL.InputArray.DPV1AlarmIndication.AlarmIndication) XIC(ILX69PBM.STATUS.DPV1AlarmIndication.AlarmIndication) OTU(ILX69PBM.STATUS.DPV1AlarmIndication.AlarmIndication) ] ,[XIC(UTIL.InputArray.DPV1AlarmIndication.AlarmOverrun) XIO(ILX69PBM.STATUS.DPV1AlarmIndication.AlarmOverrun) OTL(ILX69PBM.STATUS.DPV1AlarmIndication.AlarmOverrun) ,XIO(UTIL.InputArray.DPV1AlarmIndication.AlarmOverrun) XIC(ILX69PBM.STATUS.DPV1AlarmIndication.AlarmOverrun) OTU(ILX69PBM.STATUS.DPV1AlarmIndication.AlarmOverrun) ] ,COP(UTIL.InputArray.DPV1AlarmIndication.AlarmIndicationCounter,ILX69PBM.STATUS.DPV1AlarmIndication.AlarmIndicationCounter,6) ] ,[SIZE(Connection_Input[0],0,UTIL.InputSize) CPT(UTIL.InputSize,(UTIL.InputSize-44)*2) SIZE(ILX69PBM.DATA.INPUT[0],0,UTIL.InputDataSize) ,[EQU(UTIL.InputArray.FirmwareRevBPSize.Input,1) MOV(0,UTIL.Config.MaxBlockTransferIn) ,GRT(UTIL.InputArray.FirmwareRevBPSize.Input,1) MOV(UTIL.InputArray.FirmwareRevBPSize.Input,UTIL.Config.MaxBlockTransferIn) ] ,[GRT(UTIL.Config.MaxBlockTransferIn,14) MOV(14,UTIL.Config.MaxBlockTransferIn) ,LES(UTIL.Config.MaxBlockTransferIn,0) MOV(0,UTIL.Config.MaxBlockTransferIn) ] ,[LES(ILX69PBM.CONTROL.BackplaneBlock.Input.BlockID,0) ,GRT(ILX69PBM.CONTROL.BackplaneBlock.Input.BlockID,UTIL.Config.MaxBlockTransferIn) ,GRT(ILX69PBM.CONTROL.BackplaneBlock.Input.BlockID,14) ] MOV(0,ILX69PBM.CONTROL.BackplaneBlock.Input.BlockID) ,NEQ(UTIL.InputSize,0) [[LES(UTIL.InputSize,408) ,LES(UTIL.InputDataSize,408) ] [LEQ(UTIL.InputSize,UTIL.InputDataSize) MOV(UTIL.InputSize,UTIL.InputCopyLength) ,GRT(UTIL.InputSize,UTIL.InputDataSize) MOV(UTIL.InputDataSize,UTIL.InputCopyLength) ,MOV(0,UTIL.Config.MaxBlockTransferIn) ] ,GEQ(UTIL.InputSize,408) GEQ(UTIL.InputDataSize,408) CPT(UTIL.InputCopyLength,UTIL.InputDataSize MOD UTIL.InputSize) EQU(UTIL.InputCopyLength,0) MOV(UTIL.InputSize,UTIL.InputCopyLength) ] ] ,GRT(UTIL.Config.MaxBlockTransferIn,0) NEQ(ILX69PBM.CONTROL.BackplaneBlock.Input.BlockID,UTIL.InputArray.DeviceStatusRegister.BlockTransferIn) OTU(ILX69PBM.STATUS.BackplaneBlock.Input.BlockRead) ,[EQU(UTIL.Config.MaxBlockTransferIn,0) MOV(0,ILX69PBM.CONTROL.BackplaneBlock.Input.BlockID) MOV(0,UTIL.InputOffset) OTL(ILX69PBM.STATUS.BackplaneBlock.Input.BlockRead) ,GRT(UTIL.Config.MaxBlockTransferIn,0) EQU(ILX69PBM.CONTROL.BackplaneBlock.Input.BlockID,UTIL.InputArray.DeviceStatusRegister.BlockTransferIn) [LIM(1,UTIL.InputArray.DeviceStatusRegister.BlockTransferIn,14) SUB(UTIL.InputArray.DeviceStatusRegister.BlockTransferIn,1,UTIL.InputArray.DeviceStatusRegister.BlockTransferIn) CPT(UTIL.InputOffset,UTIL.InputArray.DeviceStatusRegister.BlockTransferIn*UTIL.InputSize) ,XIC(ILX69PBM.STATUS.Communication) [XIO(ILX69PBM.CONTROL.BackplaneBlock.DisableAutoTransfer) [LES(ILX69PBM.CONTROL.BackplaneBlock.Input.BlockID,UTIL.Config.MaxBlockTransferIn) ADD(ILX69PBM.CONTROL.BackplaneBlock.Input.BlockID,1,ILX69PBM.CONTROL.BackplaneBlock.Input.BlockID) MOV(408,UTIL.InputCopyLength) OTL(InputBlockIDIncrementComplete) ,XIO(InputBlockIDIncrementComplete) EQU(ILX69PBM.CONTROL.BackplaneBlock.Input.BlockID,UTIL.Config.MaxBlockTransferIn) MOV(0,ILX69PBM.CONTROL.BackplaneBlock.Input.BlockID) ] ,XIC(ILX69PBM.CONTROL.BackplaneBlock.DisableAutoTransfer) ] OTL(ILX69PBM.STATUS.BackplaneBlock.Input.BlockRead) NEQ(UTIL.InputArray.DeviceStatusRegister.BlockTransferIn,0) ] ] LES(UTIL.InputOffset,UTIL.InputDataSize) COP(UTIL.InputArray.InputData[0],ILX69PBM.DATA.INPUT[UTIL.InputOffset],UTIL.InputCopyLength) ];
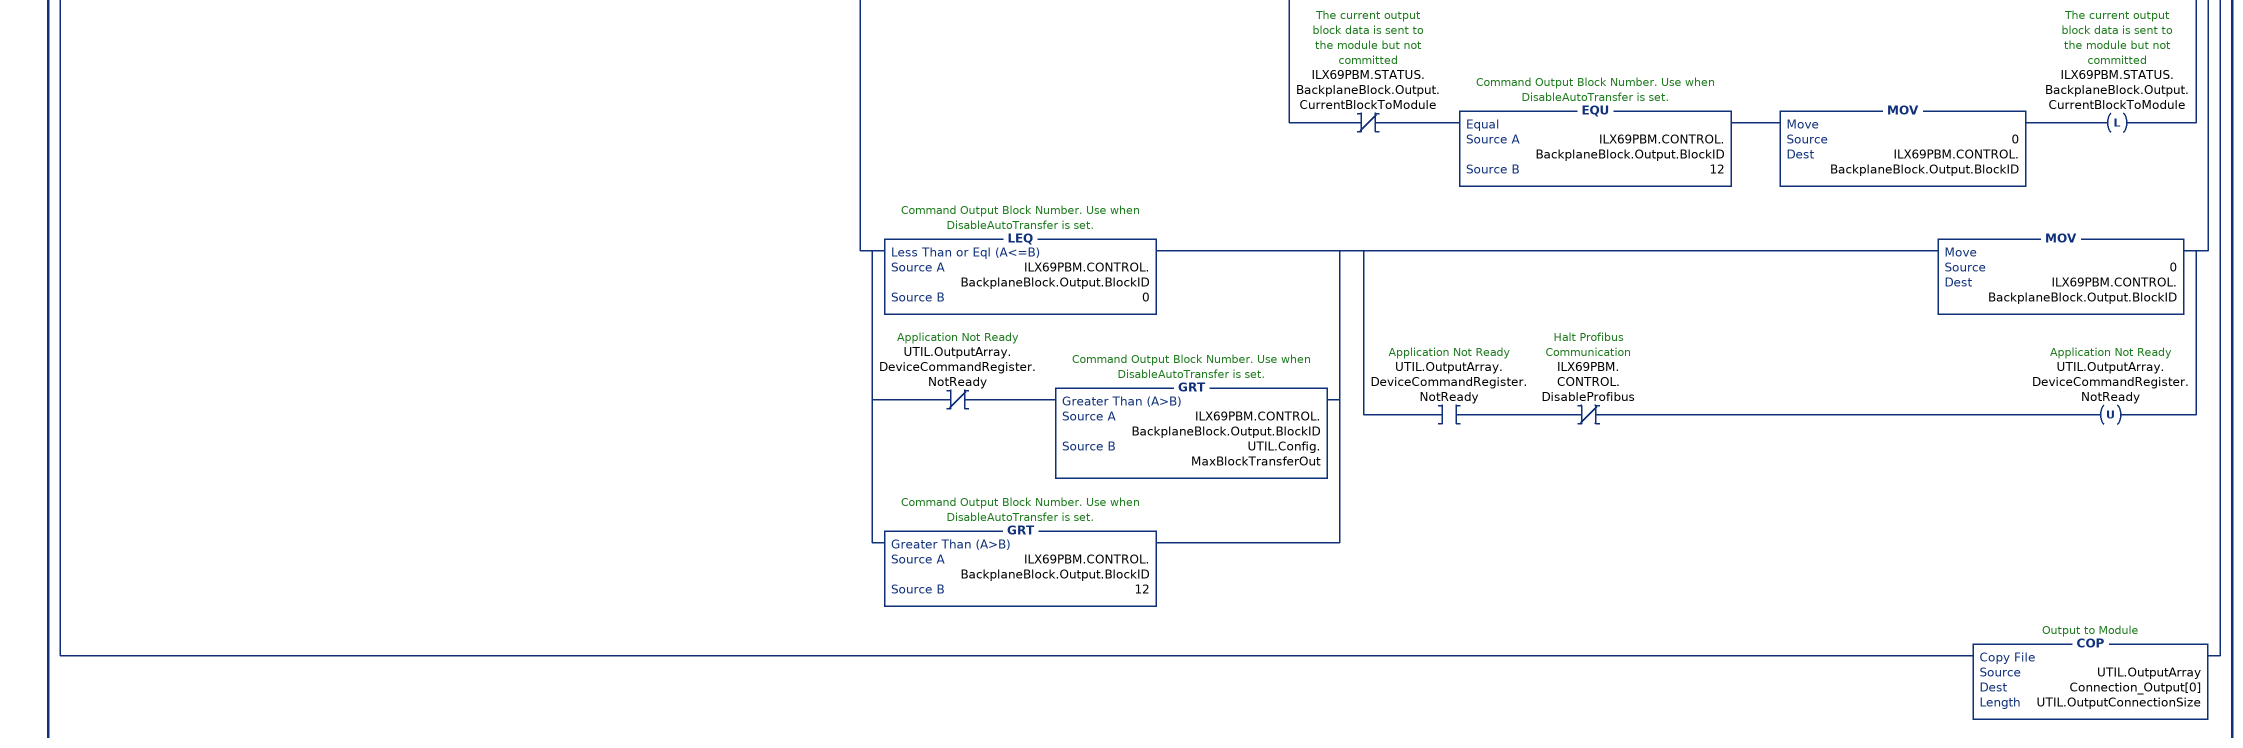
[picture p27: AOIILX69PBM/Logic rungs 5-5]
   // Handle Output Data
   5: [[[[XIC(ILX69PBM.CONTROL.DisableProfibus) XIO(UTIL.OutputArray.DeviceCommandRegister.NotReady) OTL(UTIL.OutputArray.DeviceCommandRegister.NotReady) ,XIO(ILX69PBM.CONTROL.DisableProfibus) XIC(Connection_Input[0].6) XIC(Connection_Input[0].7) OTU(UTIL.OutputArray.DeviceCommandRegister.NotReady) ] ,[XIC(ILX69PBM.CONTROL.ColdBoot) XIO(UTIL.OutputArray.DeviceCommandRegister.Reset) OTL(UTIL.OutputArray.DeviceCommandRegister.Reset) ,XIO(ILX69PBM.CONTROL.ColdBoot) XIC(UTIL.OutputArray.DeviceCommandRegister.Reset) OTU(UTIL.OutputArray.DeviceCommandRegister.Reset) ] ,[XIO(ILX69PBM.CONTROL.BackplaneBlock.DisableAutoTransfer) ,XIC(ILX69PBM.CONTROL.BackplaneBlock.DisableAutoTransfer) [XIC(ILX69PBM.CONTROL.BackplaneBlock.Output.WriteBlock) ,XIC(ILX69PBM.CONTROL.BackplaneBlock.Output.CommitToProfibus) MOV(0,ILX69PBM.CONTROL.BackplaneBlock.Output.BlockID) OTU(ILX69PBM.CONTROL.BackplaneBlock.Output.CommitToProfibus) ] ] COP(ILX69PBM.CONTROL.BackplaneBlock.Output.BlockID,UTIL.OutputArray.DeviceCommandRegister.BlockTransferOut,1) OTU(ILX69PBM.CONTROL.BackplaneBlock.Output.WriteBlock) ,[XIO(ILX69PBM.CONTROL.BackplaneBlock.DisableAutoTransfer) ,XIC(ILX69PBM.CONTROL.BackplaneBlock.DisableAutoTransfer) XIC(ILX69PBM.CONTROL.BackplaneBlock.Input.ReadBlock) ] COP(ILX69PBM.CONTROL.BackplaneBlock.Input.BlockID,UTIL.OutputArray.DeviceCommandRegister.BlockTransferIn,1) OTU(ILX69PBM.CONTROL.BackplaneBlock.Input.ReadBlock) ] ,MOV(ILX69PBM.CONTROL.SlaveDiagnostic.GetSlaveDiag.Address,UTIL.OutputArray.DiagnosticSlaveAddress.SlaveAddress) MOV(ILX69PBM.CONTROL.SlaveDiagnostic.GetSlaveDiag.Function,UTIL.OutputArray.DiagnosticSlaveAddress.DiagnosticMode) ,[MOV(ILX69PBM.CONTROL.SlaveControl.SetSlaveControl.Address,UTIL.OutputArray.GlobalControlCommand.SlaveAddress) ,[XIC(ILX69PBM.CONTROL.SlaveControl.SetSlaveControl.SlaveCommand.ClearData) XIO(UTIL.OutputArray.GlobalControlCommand.ControlCommand.1) OTL(UTIL.OutputArray.GlobalControlCommand.ControlCommand.1) ,XIO(ILX69PBM.CONTROL.SlaveControl.SetSlaveControl.SlaveCommand.ClearData) XIC(UTIL.OutputArray.GlobalControlCommand.ControlCommand.1) OTU(UTIL.OutputArray.GlobalControlCommand.ControlCommand.1) ] ,[XIC(ILX69PBM.CONTROL.SlaveControl.SetSlaveControl.SlaveCommand.UnFreeze) XIO(UTIL.OutputArray.GlobalControlCommand.ControlCommand.2) OTL(UTIL.OutputArray.GlobalControlCommand.ControlCommand.2) ,XIO(ILX69PBM.CONTROL.SlaveControl.SetSlaveControl.SlaveCommand.UnFreeze) XIC(UTIL.OutputArray.GlobalControlCommand.ControlCommand.2) OTU(UTIL.OutputArray.GlobalControlCommand.ControlCommand.2) ] ,[XIC(ILX69PBM.CONTROL.SlaveControl.SetSlaveControl.SlaveCommand.Freeze) XIO(UTIL.OutputArray.GlobalControlCommand.ControlCommand.3) OTL(UTIL.OutputArray.GlobalControlCommand.ControlCommand.3) ,XIO(ILX69PBM.CONTROL.SlaveControl.SetSlaveControl.SlaveCommand.Freeze) XIC(UTIL.OutputArray.GlobalControlCommand.ControlCommand.3) OTU(UTIL.OutputArray.GlobalControlCommand.ControlCommand.3) ] ,[XIC(ILX69PBM.CONTROL.SlaveControl.SetSlaveControl.SlaveCommand.UnSync) XIO(UTIL.OutputArray.GlobalControlCommand.ControlCommand.4) OTL(UTIL.OutputArray.GlobalControlCommand.ControlCommand.4) ,XIO(ILX69PBM.CONTROL.SlaveControl.SetSlaveControl.SlaveCommand.UnSync) XIC(UTIL.OutputArray.GlobalControlCommand.ControlCommand.4) OTU(UTIL.OutputArray.GlobalControlCommand.ControlCommand.4) ] ,[XIC(ILX69PBM.CONTROL.SlaveControl.SetSlaveControl.SlaveCommand.Sync) XIO(UTIL.OutputArray.GlobalControlCommand.ControlCommand.5) OTL(UTIL.OutputArray.GlobalControlCommand.ControlCommand.5) ,XIO(ILX69PBM.CONTROL.SlaveControl.SetSlaveControl.SlaveCommand.Sync) XIC(UTIL.OutputArray.GlobalControlCommand.ControlCommand.5) OTU(UTIL.OutputArray.GlobalControlCommand.ControlCommand.5) ] ,MOV(ILX69PBM.CONTROL.SlaveControl.SetSlaveControl.SlaveCommand.GroupSelect,UTIL.OutputArray.GlobalControlCommand.GroupSelect) ] ] ,[SIZE(Connection_Output[0],0,UTIL.OutputConnectionSize) CPT(UTIL.OutputSize,UTIL.OutputConnectionSize-8) SIZE(UTIL.OutputArray.OutputData[0],0,UTIL.UTILOutputCopyLength) SIZE(ILX69PBM.DATA.OUTPUT[0],0,UTIL.OutputDataSize) DIV(UTIL.OutputDataSize,2,UTIL.OutputDataSize) ,[[EQU(UTIL.InputArray.FirmwareRevBPSize.Output,1) MOV(0,UTIL.Config.MaxBlockTransferOut) ,GRT(UTIL.InputArray.FirmwareRevBPSize.Output,1) MOV(UTIL.InputArray.FirmwareRevBPSize.Output,UTIL.Config.MaxBlockTransferOut) ] ,GRT(UTIL.Config.MaxBlockTransferOut,12) MOV(12,UTIL.Config.MaxBlockTransferOut) ,LES(UTIL.Config.MaxBlockTransferOut,0) MOV(0,UTIL.Config.MaxBlockTransferOut) ] ,[[LES(UTIL.OutputSize,240) ,LES(UTIL.OutputDataSize,240) ] [LEQ(UTIL.OutputSize,UTIL.OutputDataSize) MOV(UTIL.OutputSize,UTIL.OutputCopyLastLength) ,GRT(UTIL.OutputSize,UTIL.OutputDataSize) MOV(UTIL.OutputDataSize,UTIL.OutputCopyLastLength) ,XIO(UTIL.OutputArray.DeviceCommandRegister.NotReady) MOV(0,UTIL.Config.MaxBlockTransferOut) ] ,GEQ(UTIL.OutputDataSize,240) GEQ(UTIL.OutputSize,240) CPT(UTIL.OutputCopyLastLength,UTIL.OutputDataSize MOD UTIL.OutputSize) XIO(UTIL.OutputArray.DeviceCommandRegister.NotReady) CPT(UTIL.Config.MaxBlockDataOut,UTIL.OutputDataSize / UTIL.OutputSize + 1) [EQU(UTIL.OutputCopyLastLength,0) [SUB(UTIL.Config.MaxBlockDataOut,1,UTIL.Config.MaxBlockDataOut) ,MOV(UTIL.OutputSize,UTIL.OutputCopyLastLength) ] ,LES(UTIL.Config.MaxBlockDataOut,UTIL.Config.MaxBlockTransferOut) MOV(UTIL.Config.MaxBlockDataOut,UTIL.Config.MaxBlockTransferOut) ] ] ,[LES(ILX69PBM.CONTROL.BackplaneBlock.Output.BlockID,0) ,XIO(UTIL.OutputArray.DeviceCommandRegister.NotReady) [GRT(ILX69PBM.CONTROL.BackplaneBlock.Output.BlockID,UTIL.Config.MaxBlockTransferOut) ,EQU(0,UTIL.Config.MaxBlockTransferOut) ] ,GRT(ILX69PBM.CONTROL.BackplaneBlock.Output.BlockID,12) ] [MOV(0,ILX69PBM.CONTROL.BackplaneBlock.Output.BlockID) ,XIC(UTIL.OutputArray.DeviceCommandRegister.NotReady) XIO(ILX69PBM.CONTROL.DisableProfibus) OTU(UTIL.OutputArray.DeviceCommandRegister.NotReady) ] ] ,[EQU(UTIL.Config.MaxBlockTransferOut,0) [MOV(0,UTIL.OutputOffset) ,MOV(UTIL.OutputCopyLastLength,UTIL.OutputCopyLength) ] OTL(ILX69PBM.STATUS.BackplaneBlock.Output.CommittedToProfibus) OTL(ILX69PBM.STATUS.BackplaneBlock.Output.CurrentBlockToModule) FLL(0,UTIL.OutputArray.OutputData[0],UTIL.UTILOutputCopyLength) ,GRT(UTIL.Config.MaxBlockTransferOut,0) NEQ(ILX69PBM.CONTROL.BackplaneBlock.Output.BlockID,UTIL.InputArray.DeviceStatusRegister.BlockTransferOut) [NEQ(ILX69PBM.CONTROL.BackplaneBlock.Output.BlockID,0) OTU(ILX69PBM.STATUS.BackplaneBlock.Output.CommittedToProfibus) ,NEQ(ILX69PBM.CONTROL.BackplaneBlock.Output.BlockID,UTIL.Config.MaxBlockTransferOut) MOV(UTIL.OutputSize,UTIL.OutputCopyLength) ,EQU(ILX69PBM.CONTROL.BackplaneBlock.Output.BlockID,UTIL.Config.MaxBlockTransferOut) MOV(UTIL.OutputCopyLastLength,UTIL.OutputCopyLength) ,OTU(ILX69PBM.STATUS.BackplaneBlock.Output.CurrentBlockToModule) ,CPT(UTIL.OutputOffset,(UTIL.OutputArray.DeviceCommandRegister.BlockTransferOut-1)*UTIL.OutputSize*2) ] ] GEQ(UTIL.OutputOffset,0) CMP(UTIL.OutputOffset<UTIL.OutputDataSize*2) COP(ILX69PBM.DATA.OUTPUT[UTIL.OutputOffset],UTIL.OutputArray.OutputData[0],UTIL.OutputCopyLength) ,GRT(UTIL.Config.MaxBlockTransferOut,0) EQU(ILX69PBM.CONTROL.BackplaneBlock.Output.BlockID,UTIL.InputArray.DeviceStatusRegister.BlockTransferOut) XIC(ILX69PBM.STATUS.Running) XIC(ILX69PBM.STATUS.Ready) [XIC(ILX69PBM.STATUS.Communication) [EQU(UTIL.InputArray.DeviceStatusRegister.BlockTransferOut,0) OTL(ILX69PBM.STATUS.BackplaneBlock.Output.CommittedToProfibus) ,[XIO(ILX69PBM.CONTROL.BackplaneBlock.DisableAutoTransfer) NEQ(ILX69PBM.CONTROL.BackplaneBlock.Output.BlockID,UTIL.Config.MaxBlockTransferOut) ADD(ILX69PBM.CONTROL.BackplaneBlock.Output.BlockID,1,ILX69PBM.CONTROL.BackplaneBlock.Output.BlockID) ,XIC(ILX69PBM.CONTROL.BackplaneBlock.DisableAutoTransfer) ] OTL(ILX69PBM.STATUS.BackplaneBlock.Output.CurrentBlockToModule) ,XIO(ILX69PBM.CONTROL.BackplaneBlock.DisableAutoTransfer) XIO(ILX69PBM.STATUS.BackplaneBlock.Output.CurrentBlockToModule) EQU(ILX69PBM.CONTROL.BackplaneBlock.Output.BlockID,UTIL.Config.MaxBlockTransferOut) MOV(0,ILX69PBM.CONTROL.BackplaneBlock.Output.BlockID) OTL(ILX69PBM.STATUS.BackplaneBlock.Output.CurrentBlockToModule) ] ,XIC(UTIL.OutputArray.DeviceCommandRegister.NotReady) XIO(ILX69PBM.CONTROL.DisableProfibus) XIO(ILX69PBM.STATUS.Communication) [NEQ(ILX69PBM.CONTROL.BackplaneBlock.Output.BlockID,12) ADD(ILX69PBM.CONTROL.BackplaneBlock.Output.BlockID,1,ILX69PBM.CONTROL.BackplaneBlock.Output.BlockID) OTL(ILX69PBM.STATUS.BackplaneBlock.Output.CurrentBlockToModule) ,XIO(ILX69PBM.STATUS.BackplaneBlock.Output.CurrentBlockToModule) EQU(ILX69PBM.CONTROL.BackplaneBlock.Output.BlockID,12) MOV(0,ILX69PBM.CONTROL.BackplaneBlock.Output.BlockID) OTL(ILX69PBM.STATUS.BackplaneBlock.Output.CurrentBlockToModule) ] ,[LEQ(ILX69PBM.CONTROL.BackplaneBlock.Output.BlockID,0) ,XIO(UTIL.OutputArray.DeviceCommandRegister.NotReady) GRT(ILX69PBM.CONTROL.BackplaneBlock.Output.BlockID,UTIL.Config.MaxBlockTransferOut) ,GRT(ILX69PBM.CONTROL.BackplaneBlock.Output.BlockID,12) ] [MOV(0,ILX69PBM.CONTROL.BackplaneBlock.Output.BlockID) ,XIC(UTIL.OutputArray.DeviceCommandRegister.NotReady) XIO(ILX69PBM.CONTROL.DisableProfibus) OTU(UTIL.OutputArray.DeviceCommandRegister.NotReady) ] ] ,COP(UTIL.OutputArray,Connection_Output[0],UTIL.OutputConnectionSize) ];
END_ROUTINE

ROUTINE Prescan   (* ladder *)
// Prescan
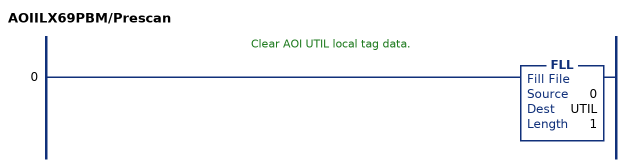
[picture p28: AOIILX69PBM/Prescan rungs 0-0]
   // Clear AOI UTIL local tag data.
   0: FLL(0,UTIL,1);
END_ROUTINE
END_ADD_ON_INSTRUCTION

VAR_GLOBAL   (* controller tags *)
   AOIILX69PBM : AOIILX69PBM;
   ILX69PBM : ILX69PBM_MODULEDEF;
   ILX69PBM_MSGDPV1Alarm : MESSAGE;   // DPV1 Alarm Response Message
        MessageParameters(ServiceCode := 16#0064, LocalElement := ILX69PBM.CONTROL.DPV1.Alarm.Request, DestinationTag := ILX69PBM.CONTROL.DPV1.Alarm.Response, ...)
   ILX69PBM_MSGDPV1Read : MESSAGE;   // DPV1 Read Message
        MessageParameters(ServiceCode := 16#0064, LocalElement := ILX69PBM.CONTROL.DPV1.Read.Request, DestinationTag := ILX69PBM.CONTROL.DPV1.Read.Response, ...)
   ILX69PBM_MSGDPV1Write : MESSAGE;   // DPV1 Write Message
        MessageParameters(ServiceCode := 16#0064, LocalElement := ILX69PBM.CONTROL.DPV1.Write.Request, DestinationTag := ILX69PBM.CONTROL.DPV1.Write.Response, ...)
   ILX69PBM_MSGSlaveControl : MESSAGE;   // Slave Control Message
        MessageParameters(ServiceCode := 16#0064, LocalElement := ILX69PBM.CONTROL.SlaveControl.SetSlaveControl_MSG.Request, DestinationTag := ILX69PBM.CONTROL.SlaveControl.SetSlaveControl_MSG.Response, ...)
   ILX69PBM_MSGSlaveDiagRequest : MESSAGE;   // Slave Diagnostic Request Message
        MessageParameters(ServiceCode := 16#0064, LocalElement := ILX69PBM.CONTROL.SlaveDiagnostic.GetSlaveDiagExtended_MSG.Request, DestinationTag := ILX69PBM.CONTROL.SlaveDiagnostic.GetSlaveDiagExtended_MSG.Response, ...)
END_VAR

PROGRAM MainProgram   (* main routine MainRoutine *)

ROUTINE MainRoutine   (* ladder *)
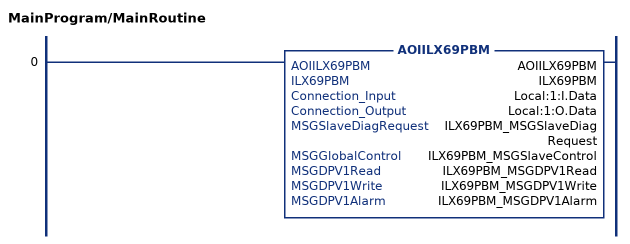
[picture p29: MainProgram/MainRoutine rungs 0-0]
   0: AOIILX69PBM(AOIILX69PBM,ILX69PBM,Local:1:I.Data,Local:1:O.Data,ILX69PBM_MSGSlaveDiagRequest,ILX69PBM_MSGSlaveControl,ILX69PBM_MSGDPV1Read,ILX69PBM_MSGDPV1Write,ILX69PBM_MSGDPV1Alarm);
END_ROUTINE
END_PROGRAM
